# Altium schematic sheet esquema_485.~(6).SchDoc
size A4
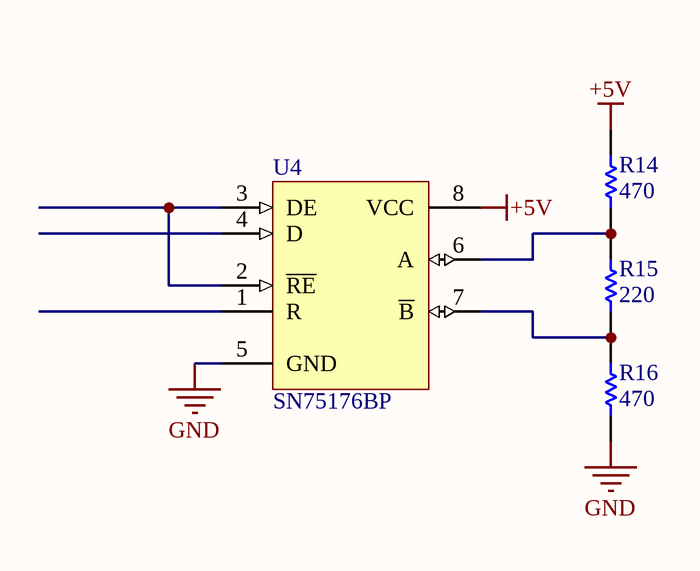
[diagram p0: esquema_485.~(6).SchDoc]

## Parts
R14  value 470  [1005[0402]]  (hidden comment: Carbon 1/8w 5%)
R15  value 220  [1005[0402]]  (hidden comment: Carbon 1/8w 5%)
R16  value 470  [1005[0402]]  (hidden comment: Carbon 1/8w 5%)
U4  SN75176BP  [P008]

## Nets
+5V: R14.2 U4.8(VCC)
GND: R16.1 U4.5(GND)
NetR14_1: R14.1 R15.2 U4.6(A)
NetR15_1: R15.1 R16.2 U4.7(~{B})
NetU4_2: U4.2(~{RE}) U4.3(DE)

Not connected (* = marked no-connect by the designer): U4 1(R) 4(D)

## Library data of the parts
R14-R16 = Res Semi: Semiconductor Resistor
U4 = SN75176BP: Differential Bus Transceiver; Note: Receiver Hysteresis of 50mV Typical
